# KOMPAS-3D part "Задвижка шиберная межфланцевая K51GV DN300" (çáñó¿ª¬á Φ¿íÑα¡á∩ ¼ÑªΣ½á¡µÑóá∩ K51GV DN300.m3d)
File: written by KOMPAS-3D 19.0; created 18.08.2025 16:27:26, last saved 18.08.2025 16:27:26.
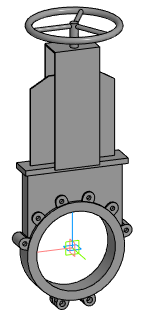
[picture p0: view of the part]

Document properties: Автор: Евгений; Полное имя файла: E:\Dendor Работа Сачек\3D для проектировщиков\2.4 Тип K51GV. Задвижка шиберная межфланцевая\stp_Задвижка шиберная K51GV DN50-400 с маховиком\Задвижка шиберная межфланцевая K51GV DN300.m3d

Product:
- Part/product: Задвижка шиберная межфланцевая K51GV DN300

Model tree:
1. Операция без истории:1  (labels: Задвижка шиберная межфланцевая K51GV DN300)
